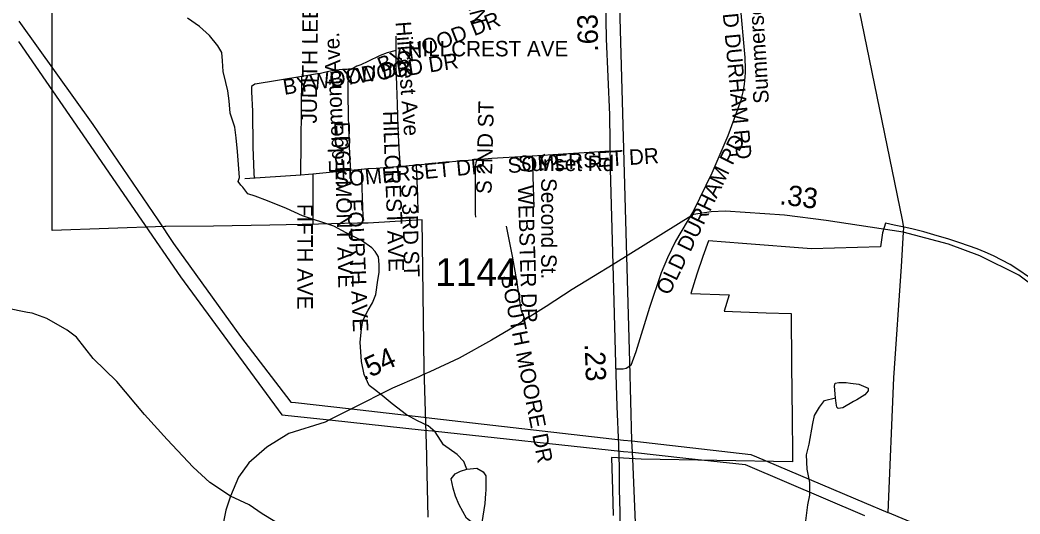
# Model space of a CAD drawing. Extents: x 1950930 to 2061844, y 904556 to 1017002.
# Drawn here: x 2001603 to 2007754, y 942619 to 945655 of the extents above; entities that cross this region are included whole.
import ezdxf

# ---------------------------------------------------------------- set-up
doc = ezdxf.new("R2010")
doc.units = 0
for name, color, linetype in [('Exist Boundary Political City Limit New', 7, 'Continuous'), ('Exist Hydrographic Misc Water Feature', 7, 'Continuous'), ('Exist Railroad Mainline', 7, 'Continuous'), ('Exist Road Non-System Type 51', 7, 'Continuous'), ('Exist Road Non-System Type 51 Label', 7, 'Continuous'), ('Exist Road Primary US Mileage Hundredths English Label', 7, 'Continuous'), ('Exist Road Primary US Structure Standard Bridge CELL', 7, 'Continuous'), ('Exist Road Secondary Mileage Hundredths English Label', 7, 'Continuous'), ('Exist Road Secondary Structure Standard Bridge Number Label', 7, 'Continuous'), ('Exist Road Secondary Type 51 Attributed', 7, 'Continuous'), ('Exist Road Secondary Type 51 Number Label', 7, 'Continuous'), ('Exist Utilities Electrical Transmission Line', 7, 'Continuous'), ('Map Preparation Boundary City Limit Buffer Line', 7, 'Continuous')]:
    doc.layers.add(name, color=color, linetype=linetype)

msp = doc.modelspace()

# ---------------------------------------------------------------- linework, layer by layer
at = {"layer": 'Exist Boundary Political City Limit New'}
for points in [[(2004114, 942598.5), (2004105.5, 942956.2), (2004105, 942977.4), (2004090.4, 943446.9), (2004088.4, 943512), (2004075.8, 944426.2), (2003744.4, 944406.2), (2003679, 944406.4), (2003439, 944400.6), (2003139.1, 944393.4), (2002793.2, 944387.8), (2002500, 944385.6), (2002494, 944385.4), (2001801, 944360.5), (2001800.9, 944594.2), (2001800.8, 945000), (2001800.5, 945594.8), (2001800.5, 945780)], [(2007812.5, 944072.8), (2007741.1, 944122.5), (2007693.2, 944151.6), (2007642.9, 944179.1), (2007591.6, 944204.7), (2007539.5, 944228.5), (2007490, 944249.4), (2007383.6, 944285.8), (2007310.2, 944309.2), (2007244.9, 944328.8), (2007162.5, 944352.1), (2007089.4, 944370.6), (2007042, 944381.6), (2006980.4, 944394.9), (2006925.6, 944405.6), (2006907.4, 944347.9), (2006896.6, 944260), (2006471.1, 944248.5), (2006047.2, 944281.2), (2005838.1, 944297.2), (2005802.1, 944201.8), (2005767.1, 944092.1), (2005729.2, 943973.5), (2005964.1, 943965.3), (2005933.8, 943864.8), (2006193, 943856.2), (2006345.8, 943851.2), (2006349.1, 943533.9), (2006352.6, 943207.2), (2006354.9, 942994.9), (2006355.5, 942939.8), (2005424.6, 942956.2), (2005242.1, 942966.4), (2005247.4, 942766.4), (2005251.5, 942610.1)]]:
    msp.add_lwpolyline(points, dxfattribs=at)
at = {"layer": 'Exist Hydrographic Misc Water Feature'}
for points in [[(2004352.2, 942894.2), (2004332.1, 942942.2), (2004292, 942984.1), (2004208.2, 943043.9), (2004156.1, 943124), (2004114.2, 943160), (2004047.9, 943191.9), (2003980, 943227.8), (2003891.8, 943295.9), (2003829.9, 943347.7), (2003783.7, 943383.8), (2003751.7, 943407.7), (2003719.7, 943475.7), (2003703.6, 943555.8), (2003699.6, 943615.9), (2003695.6, 943675.7), (2003703.8, 943755.6), (2003711.8, 943807.6), (2003743.6, 943872), (2003771.4, 943915.7), (2003791.5, 943967.8), (2003803.5, 944055.8), (2003811.4, 944103.9), (2003811.4, 944151.8), (2003807.5, 944199.8), (2003787.5, 944231.7), (2003767.3, 944253.8), (2003703.2, 944299.8), (2003609.4, 944347.6), (2003533.1, 944387.6), (2003341.1, 944451.6), (2003241.3, 944495.7), (2003125.1, 944543.4), (2003049.2, 944571.6), (2003004.9, 944587.6), (2002972.9, 944627.3), (2002961, 944639.3), (2002945.1, 944663.3), (2002953.2, 944687.4), (2002941.1, 944847.5), (2002933, 944931.4), (2002924.8, 944995.5), (2002896.7, 945083.4), (2002888.8, 945159.4), (2002880.8, 945219.3), (2002868.8, 945271.4), (2002852.5, 945339.3), (2002848.5, 945403.4), (2002844.7, 945455.3), (2002820.6, 945495.5), (2002768.4, 945559.3), (2002706.6, 945615.4), (2002632.5, 945667.4)], [(2006620, 943331.7), (2006612, 943403.4), (2006616, 943423.7), (2006640, 943427.4), (2006660, 943427.7), (2006684, 943427.5), (2006712.1, 943423.6), (2006761.9, 943415.7), (2006820.1, 943391.5), (2006820.1, 943375.8), (2006799.9, 943351.6), (2006750, 943319.5), (2006730.1, 943309.7), (2006664, 943271.7), (2006636.1, 943267.7), (2006628, 943275.4), (2006623.9, 943299.4), (2006620, 943331.7)], [(2006550.7, 942189.4), (2006528.8, 942225.3), (2006504.6, 942261.3), (2006472.5, 942343.3), (2006444.5, 942417.4), (2006444.4, 942489.3), (2006436.6, 942541.3), (2006436.4, 942577.4), (2006448.6, 942675.3), (2006460.3, 942735.4), (2006460.2, 942811.5), (2006444.2, 942895.2), (2006440.2, 942983.3), (2006456.3, 943047.3), (2006480.2, 943175.4), (2006490.1, 943223.4), (2006520, 943275.3), (2006552, 943315.4), (2006620, 943331.7)], [(2004352.2, 942894.2), (2004412.3, 942900.2), (2004452.2, 942878), (2004468.1, 942854.1), (2004468.2, 942826.2), (2004468.3, 942766.1), (2004466.2, 942744.2), (2004462.3, 942682.2), (2004444.5, 942566.1), (2004440.4, 942530.1), (2004418.5, 942530.2), (2004388.3, 942562), (2004350.2, 942594), (2004304.3, 942674), (2004282.4, 942727.9), (2004266.4, 942778.2), (2004256.1, 942834.2), (2004280.4, 942866.1), (2004312.2, 942882.2), (2004352.2, 942894.2)]]:
    msp.add_lwpolyline(points, dxfattribs=at)
at = {"layer": 'Exist Railroad Mainline'}
msp.add_line((2005353.5, 943553.1), (2005335.4, 944204.2), dxfattribs=at)
for points in [[(2005335.4, 944204.2), (2005266.5, 946693.4), (2005243.6, 947497.4)], [(2005399.9, 942321.3), (2005371.8, 942957.4), (2005370.1, 942997.7), (2005367, 943067.4), (2005366.8, 943071.4), (2005353.5, 943553.1)]]:
    msp.add_lwpolyline(points, dxfattribs=at)
at = {"layer": 'Exist Road Non-System Type 51'}
for p, q in [((2003330.2, 944702), (2003336.5, 945308.4)), ((2004753.9, 944819.2), (2004763.6, 944504)), ((2003330.2, 944702), (2002986.6, 944678.8)), ((2003702.2, 944735.7), (2003638.6, 944730))]:
    msp.add_line(p, q, dxfattribs=at)
for points in [[(2005947, 946470.8), (2005951.2, 946428.2), (2005975.8, 946245.3), (2006005, 946028.8), (2006031.2, 945765.7), (2006060.4, 945424.2), (2006062.2, 945400.7), (2006063.2, 945377.1), (2006063.6, 945353.5), (2006063.1, 945329.9), (2006061.8, 945306.3), (2006059.8, 945282.8), (2006056.9, 945259.4), (2006053.2, 945236), (2006048.9, 945212.8), (2006043.8, 945189.8), (2006037.8, 945166.9), (2006031.2, 945144.3), (2005957.8, 944942.8), (2005858.8, 944713.6), (2005745.6, 944482)], [(2003916.2, 945468.1), (2003916.2, 945479.4), (2003917.4, 945509.3), (2003916.8, 945555.9)], [(2003916.2, 945468.1), (2003861.9, 945452.8), (2003818.6, 945437.2), (2003742.1, 945400.6), (2003700, 945380.6), (2003675.5, 945370.7), (2003653.4, 945359.6), (2003636.8, 945352.9), (2003623.5, 945352.3)], [(2003942.9, 944754.1), (2003935.5, 944860.7), (2003928.5, 944995), (2003925.6, 945137.7), (2003920.1, 945252.9), (2003917.5, 945368.5), (2003916.2, 945418.5), (2003916.2, 945468.1)], [(2003623.5, 945352.3), (2003612.4, 945351.8), (2003585.8, 945351.8), (2003544.6, 945347.4), (2003491.5, 945337.4), (2003442.6, 945325.2), (2003432.8, 945324.1), (2003336.5, 945308.4)], [(2003638.6, 944730), (2003632.8, 944827.9), (2003628.5, 944938.7), (2003623.6, 945061.3), (2003620.8, 945203.6), (2003623.5, 945352.3)], [(2003047.8, 945261.4), (2003027.1, 945246.8), (2003026, 945214), (2003032.8, 945094.1), (2003036.1, 944875.6), (2003041.8, 944713.8), (2003043.4, 944682.6), (2003043.2, 944682.6)], [(2003336.5, 945308.4), (2003049.8, 945261.4), (2003047.8, 945261.4)], [(2005233.4, 944848), (2004944.6, 944831), (2004753.9, 944819.2)], [(2004040.6, 944763.1), (2003954.2, 944754.9), (2003942.9, 944754.1)], [(2004413.9, 944796.4), (2004283.9, 944784.5), (2004069.4, 944765.8), (2004040.6, 944763.1)], [(2004040.6, 944763.1), (2004047, 944572.9), (2004049.6, 944469.2)], [(2004413.9, 944796.4), (2004406.5, 944777.4), (2004403.4, 944752.7), (2004402.2, 944681.8), (2004402.2, 944564.7), (2004402, 944463.9), (2004404.2, 944444.2)], [(2004753.9, 944819.2), (2004717, 944816.9), (2004506, 944804.9), (2004413.9, 944796.4)], [(2003404.4, 944707.8), (2003377.1, 944705.2), (2003330.2, 944702)], [(2003638.6, 944730), (2003611.9, 944727.6), (2003404.4, 944707.8)], [(2003404.4, 944707.8), (2003404.4, 944405.8), (2003404.4, 944403.8)], [(2003942.9, 944754.1), (2003793.8, 944743.1), (2003742.9, 944739.4), (2003702.2, 944735.7)], [(2003702.2, 944735.7), (2003712.4, 944448.6), (2003716.2, 944423.3)], [(2005745.6, 944482), (2005634, 944295.9), (2005584.8, 944194.1), (2005546.8, 944101.3), (2005475.9, 943889), (2005391.2, 943616), (2005359.8, 943532.2), (2005331.5, 943514), (2005312.5, 943509), (2005271.4, 943507.9)], [(2004709.9, 943811.2), (2004686.8, 943868.1), (2004677.6, 943929.1), (2004660.9, 944042), (2004631.9, 944203.8), (2004595.2, 944388.4)]]:
    msp.add_lwpolyline(points, dxfattribs=at)
at = {"layer": 'Exist Road Secondary Structure Standard Bridge Number Label'}
for points in [[(2005251.2, 944151.8), (2005235.3, 944738.5), (2005230, 945072.3), (2005211.1, 945539.4), (2005204.3, 945886.9), (2005187.6, 946413.7), (2005171.8, 947021.6), (2005158.9, 947325.2), (2005165.2, 947502)], [(2005293.6, 942331.9), (2005295.1, 942386.4), (2005295, 942629.3), (2005289.8, 942771.8), (2005289.8, 942905), (2005286.8, 943041.3), (2005276.9, 943279.7), (2005267.9, 943544.7), (2005251.2, 944151.8)]]:
    msp.add_lwpolyline(points, dxfattribs=at)
at = {"layer": 'Exist Road Secondary Type 51 Attributed'}
for points in [[(2009563.2, 942851.5), (2009489, 942885.3), (2009366.8, 942951.8), (2009232.6, 942995.5), (2009026.6, 943103.4), (2008857.9, 943182.6), (2008730.3, 943255.1), (2008618.3, 943351), (2008495.3, 943438.6), (2008393.5, 943529.1), (2008227.4, 943661), (2008136.3, 943763.1), (2007910.2, 943963), (2007746.2, 944086.8), (2007506.2, 944206.6), (2007314, 944276.6), (2007036.1, 944351), (2006560.8, 944423.2), (2006305.9, 944455.9), (2005941.9, 944479.8), (2005854, 944475.6), (2005745.7, 944460.2), (2005251.2, 944151.8)], [(2005251.2, 944151.8), (2005130.2, 944079.3), (2005000.1, 943999.2), (2004839.7, 943893.6), (2004707.4, 943812.3), (2004653.2, 943774.6), (2004503.5, 943686.5), (2004304.9, 943576.6), (2004123.1, 943493.3), (2004084.5, 943475.6), (2004055.2, 943462.2), (2003894.7, 943392.1), (2003641.7, 943264.6), (2003506.7, 943196.5), (2003481, 943183.5), (2003256.6, 943114), (2003120.8, 943030), (2003009.7, 942933.7), (2002946.5, 942844.9), (2002898.4, 942728.2)], [(2002898.4, 942728.2), (2002771.7, 942812.9), (2002668.6, 942907), (2002507.7, 943077.1), (2002368.5, 943230), (2002198, 943433.9), (2002053.8, 943573.9), (2001950.3, 943705.1), (2001894.2, 943749.1), (2001767.5, 943819.4), (2001677.3, 943852.5), (2001650.2, 943857.1), (2001518.9, 943884.5)], [(2002898.4, 942728.2), (2002868.9, 942641.7), (2002823.1, 942417.8), (2002789.3, 942261.6), (2002761.2, 942113.6), (2002737.4, 941961.6), (2002713.4, 941841.7), (2002679.5, 941712.9), (2002677.5, 941705.6), (2002649.6, 941621.5), (2002631.6, 941573.5), (2002604.4, 941505.4)], [(2004649.4, 941585.5), (2004537.1, 941686.8), (2004397.5, 941819.6), (2004271.1, 941923.5), (2004162.8, 942007.8), (2004102.8, 942045), (2004024.4, 942093.6), (2003743.1, 942217.8), (2003598.7, 942280.3), (2003519.7, 942336.8), (2003422.3, 942410.2), (2003343.3, 942469.6), (2003238.8, 942530.6), (2003092.5, 942619.1), (2003012, 942674), (2002898.4, 942728.2)]]:
    msp.add_lwpolyline(points, dxfattribs=at)
at = {"layer": 'Exist Utilities Electrical Transmission Line'}
for p, q in [((2007036.1, 944351), (2007022, 944139.4)), ((2003641.7, 943264.6), (2004087.8, 943213.6)), ((2003506.7, 943196.5), (2004088.8, 943134.4)), ((2004087.8, 943213.6), (2004136.2, 943208.1)), ((2004136.2, 943208.1), (2005315.1, 943073.3)), ((2004088.8, 943134.4), (2004139.8, 943129)), ((2004139.8, 943129), (2005316, 943003.4)), ((2005315.1, 943073.3), (2005367, 943067.4)), ((2005316, 943003.4), (2005370.1, 942997.7)), ((2005370.1, 942997.7), (2005698.2, 942962.6)), ((2006132.5, 942969.6), (2006796.3, 942689.4)), ((2006796.3, 942689.4), (2006941, 942628.3))]:
    msp.add_line(p, q, dxfattribs=at)
for points in [[(2006616.9, 946330.2), (2006628.9, 946280.3), (2006717, 945944.4), (2007028.4, 944427.3)], [(2001595.7, 945647.9), (2002051.6, 945013.4), (2002450, 944426.1)], [(2001594.2, 945522.7), (2001971.6, 944975.2), (2002350.6, 944424.1)], [(2002350.6, 944424.1), (2002590.2, 944075.6), (2003212.6, 943227.9), (2003506.7, 943196.5)], [(2002450, 944426.1), (2002548, 944281.5), (2002960.3, 943709.9), (2003268.6, 943306), (2003296.6, 943304), (2003641.7, 943264.6)], [(2007028.4, 944427.3), (2007038.1, 944380.3), (2007036.1, 944351)], [(2007022, 944139.4), (2006976.5, 943456.4), (2006941, 942628.3)], [(2005367, 943067.4), (2006098.8, 942983.8), (2006132.5, 942969.6)], [(2005698.2, 942962.6), (2006062.9, 942923.7), (2006797, 942609.1)], [(2009065.6, 941712.9), (2007759.3, 942284.7), (2006941, 942628.3)]]:
    msp.add_lwpolyline(points, dxfattribs=at)
at = {"layer": 'Map Preparation Boundary City Limit Buffer Line'}
for points in [[(2004114, 942598.5), (2004105.5, 942956.2), (2004105, 942977.4), (2004090.4, 943446.9), (2004088.4, 943512), (2004075.8, 944426.2), (2003744.4, 944406.2), (2003679, 944406.4), (2003439, 944400.6), (2003139.1, 944393.4), (2002793.2, 944387.8), (2002500, 944385.6), (2002494, 944385.4), (2001801, 944360.5), (2001800.9, 944594.2), (2001800.8, 945000), (2001800.5, 945594.8), (2001800.5, 945780)], [(2007812.5, 944072.8), (2007741.1, 944122.5), (2007693.2, 944151.6), (2007642.9, 944179.1), (2007591.6, 944204.7), (2007539.5, 944228.5), (2007490, 944249.4), (2007383.6, 944285.8), (2007310.2, 944309.2), (2007244.9, 944328.8), (2007162.5, 944352.1), (2007089.4, 944370.6), (2007042, 944381.6), (2006980.4, 944394.9), (2006925.6, 944405.6), (2006907.4, 944347.9), (2006896.6, 944260), (2006471.1, 944248.5), (2006047.2, 944281.2), (2005838.1, 944297.2), (2005802.1, 944201.8), (2005767.1, 944092.1), (2005729.2, 943973.5), (2005964.1, 943965.3), (2005933.8, 943864.8), (2006193, 943856.2), (2006345.8, 943851.2), (2006349.1, 943533.9), (2006352.6, 943207.2), (2006354.9, 942994.9), (2006355.5, 942939.8), (2005424.6, 942956.2), (2005242.1, 942966.4), (2005247.4, 942766.4), (2005251.5, 942610.1)]]:
    msp.add_lwpolyline(points, dxfattribs=at)

# ---------------------------------------------------------------- texts
at = {"layer": 'Exist Road Non-System Type 51 Label'}
for s, rotation, p in [('  BRITTANY LN', 284.89933, (2004158.6, 946485.1)), ('  BRITTANY LN', 284.89933, (2004158.6, 946485.1)), ('Summerset Rd.', 93.54914, (2006210.2, 945144.4)), ('  JUDITH LEE LN', 89.42482, (2003427.8, 944948.2)), ('  OLD DURHAM RD', 275.42477, (2005902.6, 945933)), ('  BYWOOD DR', 21.52838, (2003759.4, 945303.9)), ('Hillcrest Ave', 274.3128, (2003913.2, 945643)), ('Edgemont Ave.', 92.28889, (2003600.3, 944714.3)), ('  BYWOOD DR', 8.67625, (2003446.2, 945229.1)), ('  BYWOOD DR', 9.28076, (2003159.4, 945183.3)), ('S 2ND ST', 88.48115, (2004503.2, 944584.8)), ('  HILLCREST AVE', 272.10961, (2003832.5, 945165.2)), ('  EDGEMONT AVE', 271.40575, (2003534.6, 945100)), ('  OLD DURHAM RD', 64.00984, (2005565.2, 943894.5)), ('  SOMERSET DR', 3.80978, (2004534.8, 944709.3)), ('S. Second St.', 270, (2004808.8, 944838.8)), ('  SOMERSET DR', 5.42809, (2003475.2, 944619.1)), ('S 3RD ST', 271.76578, (2003949.2, 944645.7)), ('  WEBSTER DR', 271.78434, (2004662.2, 944708.8)), ('  FOURTH AVE', 272.56104, (2003612.1, 944624.2)), ('  FIFTH AVE', 270, (2003309.4, 944595.6)), ('  SOUTH MOORE DR', 281.23496, (2004545.7, 944150.2))]:
    msp.add_text(s, height=95, rotation=rotation, dxfattribs=at).set_placement(p)
for s, p in [('  HILLCREST AVE', (2003916.5, 945431.7)), ('Sunset Rd', (2004664.7, 944726.8))]:
    msp.add_text(s, height=95, dxfattribs=at).set_placement(p)
at = {"layer": 'Exist Road Primary US Mileage Hundredths English Label'}
for s, rotation, p in [('.63', 91.12283, (2005159.6, 945460.3)), ('.23', 271.96306, (2005076.2, 943663.8))]:
    msp.add_text(s, height=125, rotation=rotation, dxfattribs=at).set_placement(p)
at = {"layer": 'Exist Road Primary US Structure Standard Bridge CELL'}
msp.add_text('.54', height=125, rotation=24.61914, dxfattribs=at).set_placement((2003715.8, 943437.6))
at = {"layer": 'Exist Road Secondary Mileage Hundredths English Label'}
msp.add_text('.33', height=125, rotation=352.70016, dxfattribs=at).set_placement((2006271.2, 944523.4))
at = {"layer": 'Exist Road Secondary Type 51 Number Label'}
msp.add_text('1144', height=170, dxfattribs=at).set_placement((2004157.5, 944020.6))

doc.saveas('drawing.dxf')
